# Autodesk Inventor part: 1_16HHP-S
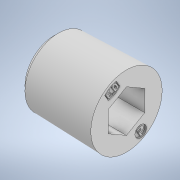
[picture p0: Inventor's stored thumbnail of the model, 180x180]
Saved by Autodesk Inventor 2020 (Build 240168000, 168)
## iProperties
Created: 2019-12
Part Number: 1_16HHP-S
Material: Generico
Description: STEP AP203
Document SubType Name: Modeling
Designer: carlo
Density: 1 g/cm^3
Appearance: Default
DataBaseUnit: MM
Title: p:/temp/worker_126/temp/exporttempdir_1508_1443_G1Pk3/format_0/Adapters Hexagon socket plug 1_16HHP-S.stp
Revision Number: NONE
Sending System: PARTsolutions
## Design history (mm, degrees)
feature "_Adapters Hexagon socket plug 1_16HHP-S"
node "Solido1"
